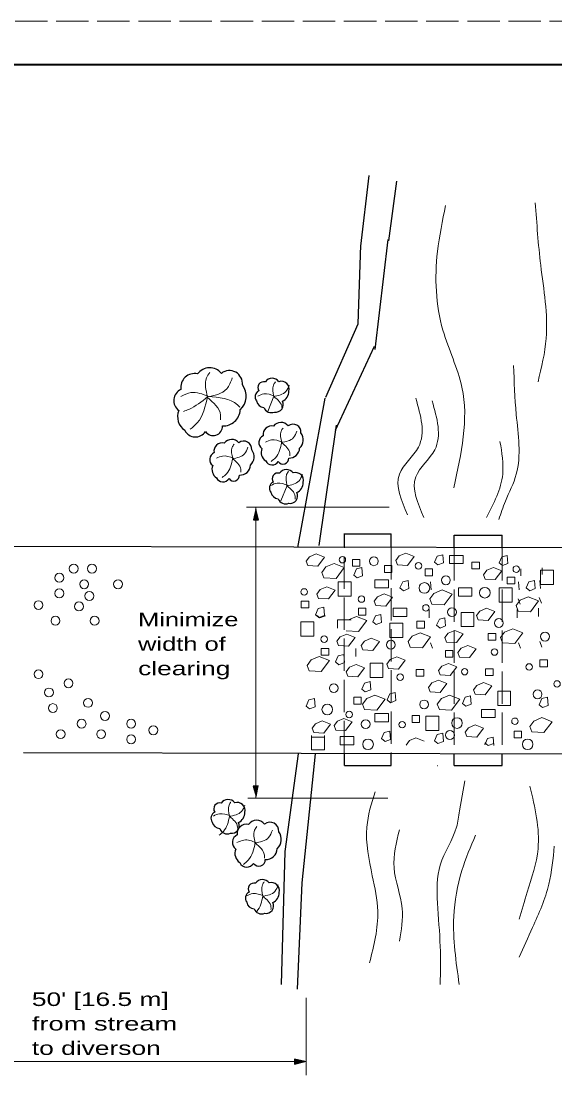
# Model space of a CAD drawing. Extents: x 1083.1 to 1117.1, y 719.4 to 741.4.
# Drawn here: x 1090.39 to 1096.52, y 729.24 to 741.35 of the extents above; entities that cross this region are included whole.
import ezdxf

# ---------------------------------------------------------------- set-up
doc = ezdxf.new("R2010")
doc.units = 0
doc.header["$LTSCALE"] = 0.062
doc.linetypes.add('LONG_DASHED', pattern=[7.5, 6, -1.5])
doc.layers.add('1', color=7, linetype='Continuous', lineweight=13)

msp = doc.modelspace()

# ---------------------------------------------------------------- hatches: boundary and pattern name
at = {"layer": '1'}
for points in [[(1093.11758, 735.62492), (1093.08817, 735.74242), (1093.05875, 735.62492)], [(1093.05475, 732.56575), (1093.09192, 732.4505), (1093.11342, 732.56967)], [(1093.53008, 729.37117), (1093.64758, 729.4005), (1093.53008, 729.42983)]]:
    msp.add_hatch(color=256, dxfattribs=at).paths.add_polyline_path(points)

# ---------------------------------------------------------------- linework, layer by layer
at = {"layer": '1', "lineweight": 25}
for p, q in [((1085.12642, 740.85408), (1116.62642, 740.85408)), ((1094.29367, 738.76867), (1094.38725, 739.57933)), ((1094.61208, 738.831), (1094.70558, 739.517)), ((1094.45675, 737.58333), (1094.6055, 738.84408)), ((1094.00217, 736.65517), (1094.44908, 737.62033)), ((1093.56992, 735.3075), (1093.88175, 737.0225)), ((1093.81358, 735.32825), (1094.01133, 736.71067)), ((1094.09483, 735.46467), (1094.64058, 735.46467)), ((1094.10242, 735.31258), (1094.10242, 735.46467)), ((1094.64058, 735.31258), (1094.64058, 735.46467)), ((1095.36258, 735.4505), (1095.91392, 735.4505)), ((1095.36258, 735.29842), (1095.36258, 735.4505)), ((1095.91392, 735.29842), (1095.91392, 735.4505)), ((1090.24975, 735.32317), (1097.05567, 735.3075)), ((1090.42133, 732.95158), (1097.07958, 732.93758)), ((1093.76775, 732.93767), (1093.61583, 731.45642)), ((1094.10242, 732.8025), (1094.10242, 732.94442)), ((1094.64058, 732.8025), (1094.64058, 732.94233)), ((1095.36258, 732.8025), (1095.36258, 732.92817)), ((1095.91392, 732.8025), (1095.91392, 732.92817)), ((1094.10242, 732.8025), (1094.64058, 732.8025)), ((1095.17283, 732.8025), (1095.17392, 732.8025)), ((1095.36258, 732.8025), (1095.91392, 732.8025)), ((1093.61583, 731.45642), (1093.56258, 730.23192))]:
    msp.add_line(p, q, dxfattribs=at)
at = {"layer": '1', "lineweight": 40}
msp.add_line((1085.12642, 740.85408), (1116.62642, 740.85408), dxfattribs=at)
at = {"layer": '1'}
for p, q in [((1093.29492, 737.04633), (1093.22283, 736.86758)), ((1093.44667, 736.02042), (1093.37458, 735.84167)), ((1094.61608, 735.7705), (1092.979, 735.7705)), ((1093.08817, 735.7705), (1093.08817, 732.42792)), ((1096.12692, 735.06058), (1096.12692, 734.98258)), ((1096.37133, 735.07475), (1096.37133, 734.99675)), ((1095.09842, 734.82025), (1095.09067, 734.91383)), ((1096.11042, 734.82025), (1096.10267, 734.91383)), ((1096.35483, 734.83442), (1096.34708, 734.928)), ((1096.09575, 734.71742), (1096.11917, 734.65508)), ((1096.34017, 734.73158), (1096.36358, 734.66925)), ((1095.075, 734.59408), (1095.075, 734.5005)), ((1096.087, 734.59408), (1096.087, 734.5005)), ((1096.33142, 734.60825), (1096.33142, 734.51467)), ((1094.02517, 734.47567), (1094.18108, 734.47567)), ((1094.02517, 734.38208), (1094.02517, 734.47567)), ((1094.24183, 734.51467), (1094.14833, 734.47567)), ((1095.09067, 734.212), (1095.11408, 734.14967)), ((1096.10267, 734.212), (1096.12608, 734.14967)), ((1096.34708, 734.22617), (1096.3705, 734.16383)), ((1094.23558, 734.0545), (1094.23558, 734.14808)), ((1093.72742, 733.12658), (1093.87558, 733.12658)), ((1095.01983, 733.08175), (1094.92467, 733.12)), ((1095.8165, 733.033), (1095.80875, 733.12658)), ((1094.64058, 732.8025), (1094.64058, 732.82025)), ((1095.48367, 732.62583), (1095.42275, 732.28075)), ((1094.60042, 732.42792), (1092.99458, 732.42792)), ((1093.66375, 730.1335), (1093.66375, 729.2445)), ((1089.09142, 729.4005), (1093.66375, 729.4005))]:
    msp.add_line(p, q, dxfattribs=at)
at = {"layer": '1', "linetype": 'LONG_DASHED'}
for p, q in [((1094.09867, 732.94442), (1094.10242, 735.31258)), ((1094.64058, 735.31258), (1094.64058, 732.94233)), ((1095.36258, 735.29842), (1095.36258, 732.92817)), ((1095.91392, 735.29842), (1095.91392, 732.92817))]:
    msp.add_line(p, q, dxfattribs=at)
msp.add_lwpolyline([(1083.12642, 719.35408), (1117.12642, 719.35408), (1117.12642, 741.35408), (1083.12642, 741.35408)], close=True, dxfattribs=at)
at = {"layer": '1', "lineweight": 40}
msp.add_lwpolyline([(1116.62642, 719.85408), (1085.12642, 719.85408), (1085.12642, 740.85408), (1116.62642, 740.85408)], dxfattribs=at)
at = {"layer": '1', "lineweight": 25}
for points in [[(1093.88833, 737.03558), (1094.2625, 737.87742), (1094.29367, 738.78175)], [(1093.57392, 732.93767), (1093.418, 731.81517), (1093.37842, 730.28658)]]:
    msp.add_lwpolyline(points, dxfattribs=at)
for points in [[(1093.11758, 735.62492), (1093.08817, 735.74242), (1093.05875, 735.62492)], [(1093.05475, 732.56575), (1093.09192, 732.4505), (1093.11342, 732.56967)], [(1093.53008, 729.37117), (1093.64758, 729.4005), (1093.53008, 729.42983)]]:
    msp.add_lwpolyline(points, close=True, dxfattribs=at)
at = {"layer": '1'}
for points in [[(1093.77792, 735.23342), (1093.70183, 735.20167), (1093.66367, 735.15075), (1093.68275, 735.09992), (1093.79692, 735.09358), (1093.87308, 735.19517)], [(1094.19508, 735.16975), (1094.28083, 735.16975), (1094.28083, 735.09175), (1094.19508, 735.09175)], [(1094.80767, 735.24117), (1094.73158, 735.20942), (1094.69342, 735.1585), (1094.7125, 735.10767), (1094.82667, 735.10133), (1094.90283, 735.20292)], [(1095.23192, 735.22433), (1095.1695, 735.20875), (1095.13833, 735.13858), (1095.17733, 735.10742), (1095.23967, 735.13075)], [(1095.30975, 735.21658), (1095.46567, 735.21658), (1095.46567, 735.123), (1095.30975, 735.123)], [(1095.9725, 735.2165), (1095.91008, 735.20092), (1095.87892, 735.13075), (1095.91792, 735.09958), (1095.98025, 735.12292)], [(1093.98458, 735.123), (1093.89108, 735.084), (1093.84425, 735.02158), (1093.86767, 734.95925), (1094.008, 734.95142), (1094.1015, 735.07617)], [(1094.30425, 735.07617), (1094.24183, 735.06058), (1094.21067, 734.99042), (1094.24967, 734.95925), (1094.312, 734.98258)], [(1094.5615, 735.09958), (1094.64725, 735.09958), (1094.64725, 735.02158), (1094.5615, 735.02158)], [(1095.02917, 735.06058), (1095.11492, 735.06058), (1095.11492, 734.98258), (1095.02917, 734.98258)], [(1095.56708, 735.13858), (1095.65283, 735.13858), (1095.65283, 735.06058), (1095.56708, 735.06058)], [(1095.81333, 735.07733), (1095.73725, 735.04558), (1095.69908, 734.99467), (1095.71817, 734.94383), (1095.83233, 734.9375), (1095.9085, 735.03908)], [(1096.35442, 735.045), (1096.50258, 735.045), (1096.50258, 734.88125), (1096.35442, 734.88125)], [(1094.03142, 734.91242), (1094.17958, 734.91242), (1094.17958, 734.74867), (1094.03142, 734.74867)], [(1094.45233, 734.93583), (1094.60825, 734.93583), (1094.60825, 734.84225), (1094.45233, 734.84225)], [(1094.83433, 734.928), (1094.77192, 734.91242), (1094.74075, 734.84225), (1094.77975, 734.81108), (1094.84208, 734.83442)], [(1095.97242, 734.967), (1096.05817, 734.967), (1096.05817, 734.889), (1095.97242, 734.889)], [(1096.28425, 734.928), (1096.22183, 734.91242), (1096.19067, 734.84225), (1096.22967, 734.81108), (1096.292, 734.83442)], [(1093.90117, 734.85542), (1093.82508, 734.82367), (1093.78692, 734.77275), (1093.806, 734.72192), (1093.92017, 734.71558), (1093.99633, 734.81717)], [(1095.22408, 734.81883), (1095.13058, 734.77983), (1095.08375, 734.71742), (1095.10717, 734.65508), (1095.2475, 734.64725), (1095.341, 734.772)], [(1095.41117, 734.84225), (1095.56708, 734.84225), (1095.56708, 734.74867), (1095.41117, 734.74867)], [(1095.87892, 734.84225), (1096.02708, 734.84225), (1096.02708, 734.6785), (1095.87892, 734.6785)], [(1093.60817, 734.6905), (1093.69392, 734.6905), (1093.69392, 734.6125), (1093.60817, 734.6125)], [(1094.55825, 734.77325), (1094.48217, 734.7415), (1094.444, 734.69058), (1094.46308, 734.63975), (1094.57725, 734.63342), (1094.65342, 734.735)], [(1096.21408, 734.74083), (1096.12058, 734.70183), (1096.07375, 734.63942), (1096.09717, 734.57708), (1096.2375, 734.56925), (1096.331, 734.694)], [(1093.86542, 734.62025), (1093.803, 734.60467), (1093.77183, 734.5345), (1093.81083, 734.50333), (1093.87317, 734.52667)], [(1094.26525, 734.60833), (1094.351, 734.60833), (1094.351, 734.53033), (1094.26525, 734.53033)], [(1094.66275, 734.60825), (1094.81867, 734.60825), (1094.81867, 734.51467), (1094.66275, 734.51467)], [(1095.44233, 734.5615), (1095.5905, 734.5615), (1095.5905, 734.39775), (1095.44233, 734.39775)], [(1095.73275, 734.60892), (1095.65667, 734.57717), (1095.6185, 734.52625), (1095.63758, 734.47542), (1095.75175, 734.46908), (1095.82792, 734.57067)], [(1093.60425, 734.45225), (1093.75242, 734.45225), (1093.75242, 734.2885), (1093.60425, 734.2885)], [(1094.5225, 734.53808), (1094.46008, 734.5225), (1094.42892, 734.45233), (1094.46792, 734.42117), (1094.53025, 734.4445)], [(1094.62383, 734.43675), (1094.772, 734.43675), (1094.772, 734.273), (1094.62383, 734.273)], [(1094.93567, 734.46017), (1095.02142, 734.46017), (1095.02142, 734.38217), (1094.93567, 734.38217)], [(1095.25525, 734.49908), (1095.19283, 734.4835), (1095.16167, 734.41333), (1095.20067, 734.38217), (1095.263, 734.4055)], [(1094.13108, 734.31308), (1094.055, 734.28133), (1094.01683, 734.23042), (1094.03592, 734.17958), (1094.15008, 734.17325), (1094.22625, 734.27483)], [(1094.97467, 734.32758), (1094.88117, 734.28858), (1094.83433, 734.22617), (1094.85775, 734.16383), (1094.99808, 734.156), (1095.09158, 734.28075)], [(1095.37133, 734.35425), (1095.29525, 734.3225), (1095.25708, 734.27158), (1095.27617, 734.22075), (1095.39033, 734.21442), (1095.4665, 734.316)], [(1095.75417, 734.31975), (1095.83992, 734.31975), (1095.83992, 734.24175), (1095.75417, 734.24175)], [(1096.03483, 734.37433), (1095.94133, 734.33533), (1095.8945, 734.27292), (1095.91792, 734.21058), (1096.05825, 734.20275), (1096.15175, 734.3275)], [(1094.41033, 734.26383), (1094.33425, 734.23208), (1094.29608, 734.18117), (1094.31517, 734.13033), (1094.42933, 734.124), (1094.5055, 734.22558)], [(1095.51925, 734.18167), (1095.44317, 734.14992), (1095.405, 734.099), (1095.42408, 734.04817), (1095.53825, 734.04183), (1095.61442, 734.14342)], [(1093.83808, 734.14817), (1093.92383, 734.14817), (1093.92383, 734.07017), (1093.83808, 734.07017)], [(1094.09533, 734.07792), (1094.03292, 734.06233), (1094.00175, 733.99217), (1094.04075, 733.961), (1094.10308, 733.98433)], [(1095.26308, 734.12483), (1095.34883, 734.12483), (1095.34883, 734.04683), (1095.26308, 734.04683)], [(1093.81467, 734.0545), (1093.72117, 734.0155), (1093.67433, 733.95308), (1093.69775, 733.89075), (1093.83808, 733.88292), (1093.93158, 734.00767)], [(1094.23867, 733.96225), (1094.16258, 733.9305), (1094.12442, 733.87958), (1094.1435, 733.82875), (1094.25767, 733.82242), (1094.33383, 733.924)], [(1094.39775, 733.97658), (1094.54592, 733.97658), (1094.54592, 733.81283), (1094.39775, 733.81283)], [(1094.70608, 734.05025), (1094.63, 734.0185), (1094.59183, 733.96758), (1094.61092, 733.91675), (1094.72508, 733.91042), (1094.80125, 734.012)], [(1095.29742, 733.97625), (1095.22133, 733.9445), (1095.18317, 733.89358), (1095.20225, 733.84275), (1095.31642, 733.83642), (1095.39258, 733.938)], [(1096.34667, 734.01567), (1096.43242, 734.01567), (1096.43242, 733.93767), (1096.34667, 733.93767)], [(1094.92783, 733.9065), (1095.01358, 733.9065), (1095.01358, 733.8285), (1094.92783, 733.8285)], [(1095.723, 733.91425), (1095.80875, 733.91425), (1095.80875, 733.83625), (1095.723, 733.83625)], [(1094.39775, 733.766), (1094.33533, 733.75042), (1094.30417, 733.68025), (1094.34317, 733.64908), (1094.4055, 733.67242)], [(1095.18192, 733.78283), (1095.10583, 733.75108), (1095.06767, 733.70017), (1095.08675, 733.64933), (1095.20092, 733.643), (1095.27708, 733.74458)], [(1095.69992, 733.75442), (1095.62383, 733.72267), (1095.58567, 733.67175), (1095.60475, 733.62092), (1095.71892, 733.61458), (1095.79508, 733.71617)], [(1094.21067, 733.58675), (1094.29642, 733.58675), (1094.29642, 733.50875), (1094.21067, 733.50875)], [(1094.45233, 733.61008), (1094.35883, 733.57108), (1094.312, 733.50867), (1094.33542, 733.44633), (1094.47575, 733.4385), (1094.56925, 733.56325)], [(1094.68625, 733.64125), (1094.62383, 733.62567), (1094.59267, 733.5555), (1094.63167, 733.52433), (1094.694, 733.54767)], [(1095.30983, 733.61008), (1095.21633, 733.57108), (1095.1695, 733.50867), (1095.19292, 733.44633), (1095.33325, 733.4385), (1095.42675, 733.56325)], [(1095.5515, 733.60225), (1095.48908, 733.58667), (1095.45792, 733.5165), (1095.49692, 733.48533), (1095.55925, 733.50867)], [(1095.86333, 733.65692), (1096.0115, 733.65692), (1096.0115, 733.49317), (1095.86333, 733.49317)], [(1096.43242, 733.58667), (1096.37, 733.57108), (1096.33883, 733.50092), (1096.37783, 733.46975), (1096.44017, 733.49308)], [(1093.75858, 733.57108), (1093.69617, 733.5555), (1093.665, 733.48533), (1093.704, 733.45417), (1093.76633, 733.4775)], [(1094.09825, 733.34358), (1094.02217, 733.31183), (1093.984, 733.26092), (1094.00308, 733.21008), (1094.11725, 733.20375), (1094.19342, 733.30533)], [(1094.45233, 733.3995), (1094.60825, 733.3995), (1094.60825, 733.30592), (1094.45233, 733.30592)], [(1094.88108, 733.37617), (1094.96683, 733.37617), (1094.96683, 733.29817), (1094.88108, 733.29817)], [(1095.037, 733.36833), (1095.18517, 733.36833), (1095.18517, 733.20458), (1095.037, 733.20458)], [(1095.67617, 733.44633), (1095.83208, 733.44633), (1095.83208, 733.35275), (1095.67617, 733.35275)], [(1096.37, 733.35275), (1096.2765, 733.31375), (1096.22967, 733.25133), (1096.25308, 733.189), (1096.39342, 733.18117), (1096.48692, 733.30592)], [(1093.84883, 733.31492), (1093.77275, 733.28317), (1093.73458, 733.23225), (1093.75367, 733.18142), (1093.86783, 733.17508), (1093.944, 733.27667)], [(1095.60283, 733.26817), (1095.52675, 733.23642), (1095.48858, 733.1855), (1095.50767, 733.13467), (1095.62183, 733.12833), (1095.698, 733.22992)], [(1094.05475, 733.13442), (1094.21067, 733.13442), (1094.21067, 733.04083), (1094.05475, 733.04083)], [(1094.62383, 733.19675), (1094.56142, 733.18117), (1094.53025, 733.111), (1094.56925, 733.07983), (1094.63158, 733.10317)], [(1095.23192, 733.17333), (1095.1695, 733.15775), (1095.13833, 733.08758), (1095.17733, 733.05642), (1095.23967, 733.07975)], [(1096.05042, 733.19683), (1096.13617, 733.19683), (1096.13617, 733.11883), (1096.05042, 733.11883)]]:
    msp.add_lwpolyline(points, close=True, dxfattribs=at)
for points in [[(1093.7835, 734.53025), (1093.8225, 734.49908), (1093.88483, 734.52242)], [(1094.12492, 734.35092), (1094.26525, 734.34308), (1094.35875, 734.46783), (1094.24183, 734.51467)], [(1093.87558, 733.1475), (1093.87558, 732.98375), (1093.72742, 732.98375), (1093.72742, 733.1475)], [(1094.92467, 733.12), (1094.84858, 733.08825), (1094.81042, 733.03733)], [(1095.80875, 733.12658), (1095.74633, 733.111), (1095.71517, 733.04083)], [(1095.71517, 733.06175), (1095.75417, 733.03058), (1095.8165, 733.05392)]]:
    msp.add_lwpolyline(points, dxfattribs=at)
for centre, radius in [((1094.08029, 735.16669), 0.03705), ((1094.44133, 735.14928), 0.05102), ((1090.99652, 735.06451), 0.05102), ((1091.20611, 735.06451), 0.05102), ((1094.95337, 735.09653), 0.03705), ((1096.07595, 735.05753), 0.03705), ((1090.83186, 734.95968), 0.05102), ((1091.11627, 734.88476), 0.05102), ((1091.50552, 734.88476), 0.05102), ((1095.26766, 734.93086), 0.05102), ((1090.83186, 734.77993), 0.05102), ((1091.17619, 734.75001), 0.05102), ((1093.64145, 734.79661), 0.03705), ((1095.02147, 734.84225), 0.06088), ((1095.71522, 734.78767), 0.06088), ((1090.59236, 734.64518), 0.05102), ((1091.05644, 734.63018), 0.05102), ((1094.29854, 734.71444), 0.03705), ((1095.03912, 734.61303), 0.03705), ((1095.33783, 734.56436), 0.05102), ((1090.78694, 734.46551), 0.05102), ((1091.23602, 734.46551), 0.05102), ((1095.87566, 734.43961), 0.05102), ((1096.40575, 734.28361), 0.05102), ((1093.87137, 734.25428), 0.03705), ((1094.63625, 734.19003), 0.05102), ((1095.82645, 734.10619), 0.03705), ((1096.22404, 733.93459), 0.03705), ((1090.59236, 733.85151), 0.05102), ((1094.74295, 733.81761), 0.03705), ((1095.48346, 733.88001), 0.03705), ((1090.93661, 733.74668), 0.05102), ((1093.98141, 733.69095), 0.05102), ((1096.54363, 733.73967), 0.03705), ((1090.71211, 733.64185), 0.05102), ((1096.32, 733.62078), 0.05102), ((1090.75702, 733.4621), 0.05102), ((1091.16119, 733.52201), 0.05102), ((1093.90672, 733.44633), 0.06088), ((1095.01816, 733.50378), 0.05102), ((1091.08636, 733.28243), 0.05102), ((1091.35577, 733.37226), 0.05102), ((1091.65519, 733.28243), 0.05102), ((1094.15829, 733.38869), 0.03705), ((1095.39563, 733.29033), 0.06088), ((1096.06037, 733.31069), 0.03705), ((1090.84686, 733.1626), 0.05102), ((1091.31086, 733.1626), 0.05102), ((1091.90969, 733.20751), 0.05102), ((1094.34783, 733.27761), 0.05102), ((1094.76629, 733.27178), 0.03705), ((1091.65519, 733.10268), 0.05102), ((1094.37438, 733.04617), 0.06088), ((1095.31441, 733.15286), 0.05102), ((1096.2063, 733.04617), 0.06088)]:
    msp.add_circle(centre, radius, dxfattribs=at)
at = {"layer": '1', "lineweight": 25}
for centre, radius, start, end in [((1092.55701, 737.19893), 0.17243, 38.98642, 143.69126), ((1092.78318, 737.18923), 0.14985, 354.15853, 127.94053), ((1092.38254, 737.14818), 0.15692, 76.91487, 189.15854), ((1093.17685, 737.14441), 0.06676, 73.45349, 214.76336), ((1093.27448, 737.15667), 0.09411, 35.96461, 146.65194), ((1093.37939, 737.12618), 0.09044, 345.02203, 108.53509), ((1092.28585, 736.99507), 0.14074, 114.43796, 233.55409), ((1092.76415, 737.04491), 0.21194, 312.33225, 37.51454), ((1093.15571, 737.03671), 0.07735, 115.82411, 216.94314), ((1093.33892, 737.10257), 0.12784, 294.97991, 0.10653), ((1093.18608, 737.01033), 0.09436, 192.30376, 265.25213), ((1093.3169, 736.94756), 0.08549, 259.54267, 27.23416), ((1092.37653, 736.81002), 0.18851, 157.59992, 236.32816), ((1092.71344, 736.89745), 0.19365, 267.14672, 357.27472), ((1093.26488, 736.94831), 0.09234, 200.28911, 293.28837), ((1093.37464, 736.63782), 0.10586, 38.98642, 143.69126), ((1093.51348, 736.63186), 0.092, 354.15853, 127.94053), ((1092.39293, 736.71075), 0.13394, 205.4749, 328.37444), ((1092.59626, 736.70056), 0.1076, 213.92462, 1.85124), ((1093.26752, 736.60667), 0.09634, 76.91487, 189.15854), ((1093.5018, 736.54327), 0.13011, 312.33225, 37.51454), ((1092.70236, 736.41175), 0.09634, 76.91487, 189.15854), ((1092.80947, 736.4429), 0.10586, 38.98642, 143.69126), ((1092.94831, 736.43695), 0.092, 354.15853, 127.94053), ((1093.20816, 736.51267), 0.0864, 114.43796, 233.55409), ((1092.643, 736.31775), 0.0864, 114.43796, 233.55409), ((1092.93663, 736.34835), 0.13011, 312.33225, 37.51454), ((1093.26383, 736.39906), 0.11573, 157.59992, 236.32816), ((1093.47067, 736.45274), 0.11888, 267.14672, 357.27472), ((1092.69867, 736.20415), 0.11573, 157.59992, 236.32816), ((1092.9055, 736.25782), 0.11888, 267.14672, 357.27472), ((1093.2739, 736.33812), 0.08223, 205.4749, 328.37444), ((1093.39873, 736.33187), 0.06606, 213.92462, 1.85124), ((1092.83356, 736.13695), 0.06606, 213.92462, 1.85124), ((1093.34063, 736.096), 0.06676, 73.45349, 214.76336), ((1093.43826, 736.10826), 0.09411, 35.96461, 146.65194), ((1093.54317, 736.07777), 0.09044, 345.02203, 108.53509), ((1092.70873, 736.1432), 0.08223, 205.4749, 328.37444), ((1093.31949, 735.9883), 0.07735, 115.82411, 216.94314), ((1093.5027, 736.05416), 0.12784, 294.97991, 0.10653), ((1093.34986, 735.96192), 0.09436, 192.30376, 265.25213), ((1093.48068, 735.89915), 0.08549, 259.54267, 27.23416), ((1093.42866, 735.8999), 0.09234, 200.28911, 293.28837), ((1092.67022, 732.30608), 0.06676, 73.45349, 214.76336), ((1092.76784, 732.31834), 0.09411, 35.96461, 146.65194), ((1092.87276, 732.28785), 0.09044, 345.02203, 108.53509), ((1092.64907, 732.19838), 0.07735, 115.82411, 216.94314), ((1092.83229, 732.26424), 0.12784, 294.97991, 0.10653), ((1092.67944, 732.172), 0.09436, 192.30376, 265.25213), ((1092.81026, 732.10924), 0.08549, 259.54267, 27.23416), ((1092.9775, 732.02234), 0.10621, 76.91487, 189.15854), ((1093.09559, 732.05668), 0.11671, 38.98642, 143.69126), ((1093.24867, 732.05012), 0.10143, 354.15853, 127.94053), ((1092.75824, 732.10998), 0.09234, 200.28911, 293.28837), ((1092.91206, 731.91871), 0.09526, 114.43796, 233.55409), ((1093.23579, 731.95244), 0.14345, 312.33225, 37.51454), ((1092.97343, 731.79346), 0.12759, 157.59992, 236.32816), ((1093.20147, 731.85263), 0.13107, 267.14672, 357.27472), ((1092.98453, 731.72626), 0.09066, 205.4749, 328.37444), ((1093.12215, 731.71937), 0.07283, 213.92462, 1.85124), ((1093.06472, 731.38583), 0.06676, 73.45349, 214.76336), ((1093.16234, 731.39809), 0.09411, 35.96461, 146.65194), ((1093.26726, 731.3676), 0.09044, 345.02203, 108.53509), ((1093.04357, 731.27813), 0.07735, 115.82411, 216.94314), ((1093.22679, 731.34399), 0.12784, 294.97991, 0.10653), ((1093.07394, 731.25175), 0.09436, 192.30376, 265.25213), ((1093.15274, 731.18973), 0.09234, 200.28911, 293.28837), ((1093.20476, 731.18899), 0.08549, 259.54267, 27.23416)]:
    msp.add_arc(centre, radius, start, end, dxfattribs=at)
at = {"layer": '1'}
for points in [[(1095.35892, 735.9935), (1095.4525, 737.14717), (1095.23417, 737.802), (1095.17183, 738.70625), (1095.26533, 739.23633)], [(1096.32558, 737.20958), (1096.41908, 737.7085), (1096.35675, 738.55033), (1096.29433, 739.26758)], [(1096.04492, 737.39667), (1096.07608, 736.83533), (1096.07608, 736.14942), (1095.95133, 735.83758), (1095.87508, 735.62783)], [(1092.53175, 737.03717), (1092.521, 737.25592), (1092.55675, 737.3185)], [(1092.521, 737.03258), (1092.75317, 737.13083), (1092.81575, 737.25592)], [(1093.29508, 737.04375), (1093.2885, 737.17242), (1093.31042, 737.20925)], [(1092.54375, 737.04217), (1092.34242, 737.08617), (1092.22633, 737.0415)], [(1093.2885, 737.041), (1093.43067, 737.09883), (1093.469, 737.17242)], [(1092.53292, 737.03767), (1092.3185, 736.89392), (1092.25808, 736.86975)], [(1092.5315, 737.04167), (1092.41383, 736.73783), (1092.3335, 736.66633)], [(1092.52992, 737.03258), (1092.68175, 736.82717), (1092.68175, 736.7735)], [(1092.53792, 737.03975), (1092.87633, 736.94467), (1092.90292, 736.91808)], [(1093.30242, 737.04667), (1093.17908, 737.07258), (1093.108, 737.04625)], [(1093.29392, 737.041), (1093.38692, 736.92017), (1093.38692, 736.88858)], [(1094.82883, 735.68167), (1094.73525, 736.14942), (1094.95358, 736.46117), (1094.92233, 737.0225)], [(1095.01592, 735.6505), (1094.92233, 736.11825), (1095.14067, 736.43), (1095.10942, 736.99133)], [(1093.38358, 736.51408), (1093.377, 736.64275), (1093.39892, 736.67958)], [(1093.377, 736.51133), (1093.51917, 736.56917), (1093.5575, 736.64275)], [(1092.82175, 736.32908), (1092.81517, 736.45775), (1092.83708, 736.49458)], [(1093.39092, 736.517), (1093.26758, 736.54292), (1093.1965, 736.51658)], [(1093.38342, 736.51667), (1093.31133, 736.33792), (1093.26217, 736.29592)], [(1093.38242, 736.51133), (1093.47542, 736.3905), (1093.47542, 736.35892)], [(1095.889, 736.52358), (1095.92017, 736.14942), (1095.73308, 735.6505)], [(1092.82908, 736.332), (1092.70575, 736.35792), (1092.63467, 736.33158)], [(1092.81517, 736.32633), (1092.95733, 736.38417), (1092.99567, 736.45775)], [(1092.82158, 736.33167), (1092.7495, 736.15292), (1092.70033, 736.11092)], [(1092.82058, 736.32633), (1092.91358, 736.2055), (1092.91358, 736.17392)], [(1093.44683, 736.01783), (1093.44025, 736.1465), (1093.46217, 736.18333)], [(1093.44025, 736.01508), (1093.58242, 736.07292), (1093.62075, 736.1465)], [(1093.45417, 736.02075), (1093.33083, 736.04667), (1093.25975, 736.02033)], [(1093.44567, 736.01508), (1093.53867, 735.89425), (1093.53867, 735.86267)], [(1094.45467, 732.50108), (1094.36108, 732.09575), (1094.4235, 731.5345), (1094.48583, 731.12917), (1094.39225, 730.53667)], [(1096.232, 732.5635), (1096.32558, 731.84633), (1096.20083, 731.34742), (1096.10725, 731.03558)], [(1092.786, 732.21975), (1092.77942, 732.34842), (1092.80133, 732.38525)], [(1092.79333, 732.22267), (1092.67, 732.24858), (1092.59892, 732.22225)], [(1092.77942, 732.217), (1092.92158, 732.27483), (1092.95992, 732.34842)], [(1095.42275, 732.28075), (1095.39008, 732.09575), (1095.203, 731.65925), (1095.17183, 731.22267), (1095.203, 730.72375), (1095.203, 730.28725)], [(1092.78583, 732.22233), (1092.71375, 732.04358), (1092.66458, 732.00158)], [(1092.78483, 732.217), (1092.87783, 732.09617), (1092.87783, 732.06458)], [(1093.0805, 731.91367), (1093.07308, 732.05892), (1093.09775, 732.1005)], [(1093.07308, 731.91058), (1093.23358, 731.97583), (1093.27683, 732.05892)], [(1094.73525, 732.06458), (1094.67292, 731.628), (1094.7665, 731.16033), (1094.73525, 730.78617)], [(1095.60833, 732.00225), (1095.4525, 731.59683), (1095.35892, 731.06675), (1095.42125, 730.28725)], [(1093.08875, 731.91692), (1092.9495, 731.94625), (1092.86925, 731.9165)], [(1093.08025, 731.91658), (1092.99892, 731.71475), (1092.94342, 731.66733)], [(1093.07917, 731.91058), (1093.18417, 731.77417), (1093.18417, 731.7385)], [(1096.10725, 730.59908), (1096.26317, 730.942), (1096.45025, 731.44092), (1096.51267, 731.8775)], [(1093.16875, 731.30183), (1093.16217, 731.4305), (1093.18408, 731.46733)], [(1093.16217, 731.29908), (1093.30433, 731.35692), (1093.34267, 731.4305)], [(1093.17608, 731.30475), (1093.05275, 731.33067), (1092.98167, 731.30433)], [(1093.16858, 731.30442), (1093.0965, 731.12567), (1093.09167, 731.1205)], [(1093.16758, 731.29908), (1093.26058, 731.17825), (1093.26058, 731.14667)]]:
    msp.add_spline(points, degree=3, dxfattribs=at)

# ---------------------------------------------------------------- texts
for s, width, p in [('Minimize', 1.4, (1091.735, 734.40175)), ('width of', 1.4, (1091.735, 734.12075)), ('clearing', 1.45, (1091.735, 733.83975)), ("50' [16.5 m]", 1.45, (1090.51567, 730.03992)), ('from stream', 1.5, (1090.51567, 729.75892)), ('to diverson', 1.45, (1090.51567, 729.47792))]:
    msp.add_text(s, height=0.156, dxfattribs=dict(at, width=width)).set_placement(p)

doc.saveas('drawing.dxf')
